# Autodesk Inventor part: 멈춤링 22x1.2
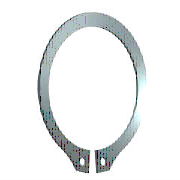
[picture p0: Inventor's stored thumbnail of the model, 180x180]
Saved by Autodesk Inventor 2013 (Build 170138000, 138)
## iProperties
IsCustomPart: 0
Created: 2015-11
Part Number: 멈춤링 22x1.2
Material: 스테인리스강
Description: 리테이닝 링(C형)
Document SubType Name: Modeling
Standard: KS B 1336
Designer: mdu
Standards Organization: KS
Language: ko-KR
Size Designation: 22 x 1.2
Categories: <MemberInstance><Categories><Category DisplayName="샤프트 부품" InternalName="7f7aeb1f-a693-4053-b835-cee3144e0d98" Mnemonic="SHFT"><Category DisplayName="써클립" Inter
Density: 8.08 g/cm^3
Mass: 1.87978 g
Surface Area: 5.91219 cm^2
Volume: 0.232646 cm^3
Author: mdu
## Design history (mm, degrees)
sketch "스케치1"
  geometry: L1 (-6, 0)-(6, 0) reference; L2 (0, 20.189)-(0, -80.536) reference; L3 (-48.09, 0)-(48.09, 0) reference; L4 (-0.5, -21.488)-(-0.5, -25.588); L5 (-0.5, -6.54)-(-0.5, -13.29); L6 (-2.795, 2.7)-(3.672, 2.7); L7 (0.5, -6.54)-(0.5, -13.29); L8 (0.5, -21.488)-(0.5, -25.588); C1 r 1 at (-2, -23.437); C2 r 1 at (2, -23.437); A1 r 10.5 centre (0, -11) between (0.5, -21.488) and (-0.5, -21.488); A2 r 13.025 centre (0, -10.325) between (5.149, -22.289) and (-5.149, -22.289); A3 r 14.597 centre (0, -11) between (-2.318, -25.411) and (-0.5, -25.588); A4 r 2 centre (-2, -23.437) between (-3.97, -23.781) and (-2.318, -25.411); A5 r 2 centre (-5.94, -24.126) between (-3.97, -23.781) and (-5.149, -22.289); A6 r 2 centre (5.94, -24.126) between (5.149, -22.289) and (3.97, -23.781); A7 r 2 centre (2, -23.437) between (2.318, -25.411) and (3.97, -23.781); A8 r 14.597 centre (0, -11) between (0.5, -25.588) and (2.318, -25.411)
  constraints: 16 point on circle, 12 end point, 10 centre point, 9 symmetric about line, 5 point on line, 4 tangent, 3 coincident, 2 horizontal, 1 perpendicular, 1 vertical, 5 other
  dimensions: "d0" = 21 diameter of A1 (= ND); "d1" = 4.1 distance of L4.end L4.start (= SRB2); "d6" = 0.5 distance between parallel lines of L2 L5 (= 0.25 x SD5); "d7" = 2.7 distance between parallel lines of L6 L3 (= SRB1); "d8" = 0.675 distance of A1.centre A2.centre (= 0.25 x SRB1); "d9" = 2 radius of A4 (= SD5); "d10" = 2 radius of A5 (= SD5); "d11" = 1.5 distance from line of L4 A4.centre (= 0.75 x SD5); "d12" = 2 diameter of C1 (= SD5); "d13" = 2 diameter of C2 (= SD5); "d14" = 11 distance from line of A1.centre L1 (= 0.5 x WD)
extrude "본체" new body sketch "스케치1" distance "d2" = 1.2 (= SD); taper "d3" = 0 deg
workaxis "Work Axis1"
workplane "Work Plane1"
body "Solid1"
other parameters: "WD" = 22 (= WDMIN) [user parameter; used in 1 equation term], "SD" = 1.2 [user parameter; used in 1 equation term], "SRB1" = 2.7 [user parameter; used in 2 equation terms], "ND" = 21 [user parameter; used in 1 equation term], "SRB2" = 4.1 [user parameter; used in 1 equation term], "SD5" = 2 [user parameter; used in 6 equation terms], "d15" = 0, "d16" = 0, "d17" = 0, "d41" = 0, "d42" = 0, "WDMIN" = 22 [user parameter; used in 1 equation term], "SD3" = 20.5 [user parameter], "WDMAX" = 24 [user parameter]
